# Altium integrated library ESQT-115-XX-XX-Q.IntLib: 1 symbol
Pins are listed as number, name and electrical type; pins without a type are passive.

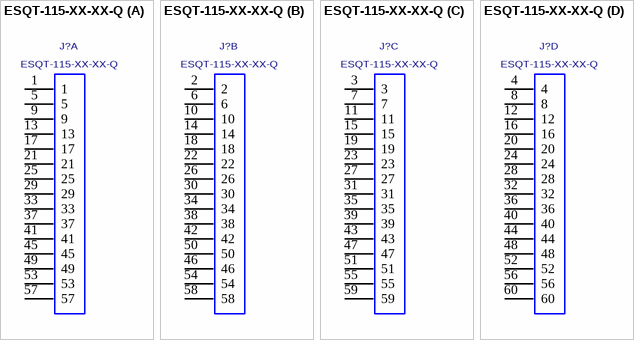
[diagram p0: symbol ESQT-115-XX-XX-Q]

## ESQT-115-XX-XX-Q
designator J?
ELEVATED SQT ASSM, QUAD ROWS.; MANUFACTURER: SAMTEC
footprint ESQT-115-XX-XX-Q
part A pins: 1, 5, 9, 13, 17, 21, 25, 29, 33, 37, 41, 45, 49, 53, 57
part B pins: 2, 6, 10, 14, 18, 22, 26, 30, 34, 38, 42, 46, 50, 54, 58
part C pins: 3, 7, 11, 15, 19, 23, 27, 31, 35, 39, 43, 47, 51, 55, 59
part D pins: 4, 8, 12, 16, 20, 24, 28, 32, 36, 40, 44, 48, 52, 56, 60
